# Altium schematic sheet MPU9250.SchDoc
size A4
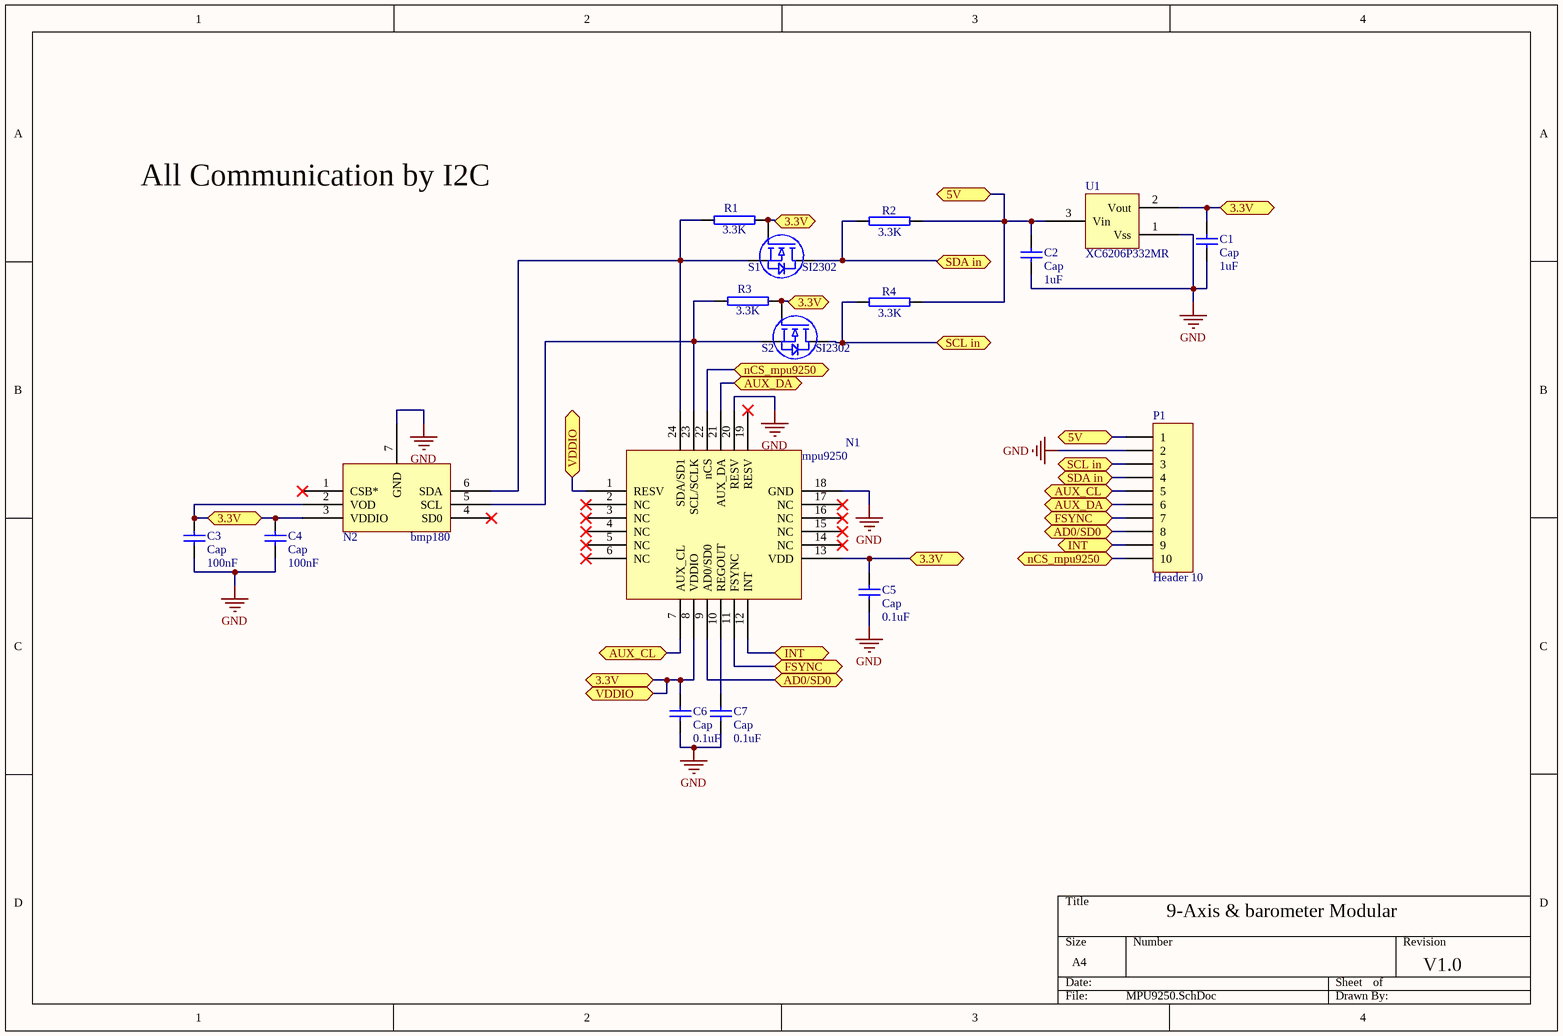
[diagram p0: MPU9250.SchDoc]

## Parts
C1  Cap  value 1uF  [CAPC_0603]
C2  Cap  value 1uF  [CAPC_0603]
C3  Cap  value 100nF  [RAD-0.3]
C4  Cap  value 100nF  [RAD-0.3]
C5  Cap  value 0.1uF  [RAD-0.3]
C6  Cap  value 0.1uF  [RAD-0.3]
C7  Cap  value 0.1uF  [RAD-0.3]
N1  mpu9250  [RM-MPU-9250A]
N2  bmp180
P1  Header 10  [HDR1X10]
R1  3.3K  [RES_0603]
R2  3.3K  [RES_0603]
R3  3.3K  [RES_0603]
R4  3.3K  [RES_0603]
S1  SI2302  [SOT-23]
S2  SI2302  [SOT-23]
U1  XC6206P332MR  [SOT-23]

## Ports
3.3V, 5V, AD0/SD0, AUX_CL, AUX_DA, FSYNC, INT, nCS_mpu9250, SCL in, SDA in (bidir), VDDIO

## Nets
GND: C1.1 C2.1 C3.1 C4.1 C5.1 C6.1 C7.1 N1.18(GND) N1.20(RESV) N2.7(GND) P1.2 U1.1(Vss)
3.3V: C1.2 C3.2 C4.2 C5.2 C6.2 N1.1(RESV) N1.8(VDDIO) N1.13(VDD) N2.2(VOD) N2.3(VDDIO) R1.1 R3.1 S1.1(G) S2.1(G) U1.2(Vout) ; port 3.3V, port VDDIO
5V: C2.2 P1.1 R2.1 R4.1 U1.3(Vin) ; port 5V
AD0/SD0: N1.9(AD0/SD0) P1.8 ; port AD0/SD0
AUX_CL: N1.7(AUX_CL) P1.5 ; port AUX_CL
AUX_DA: N1.21(AUX_DA) P1.6 ; port AUX_DA
FSYNC: N1.11(FSYNC) P1.7 ; port FSYNC
INT: N1.12(INT) P1.9 ; port INT
nCS_mpu9250: N1.22(nCS) P1.10 ; port nCS_mpu9250
SCL in: P1.3 R4.2 S2.3(D) ; port SCL in
SDA in: P1.4 R2.2 S1.3(D) ; port SDA in
NetC7_2: C7.2 N1.10(REGOUT)
NetN1_23: N1.23(SCL/SCLK) N2.5(SCL) R3.2 S2.2(S)
NetN1_24: N1.24(SDA/SD1) N2.6(SDA) R1.2 S1.2(S)

Not connected (* = marked no-connect by the designer): N1 2(NC)* 3(NC)* 4(NC)* 5(NC)* 6(NC)* 14(NC)* 15(NC)* 16(NC)* 17(NC)* 19(RESV)*; N2 1(CSB*)* 4(SD0)*

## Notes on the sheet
- All Communication by I2C
- 9-Axis & barometer Modular
- V1.0

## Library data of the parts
C1-C7 = Cap: Capacitor
N1 = mcp9250
P1 = Header 10: Header, 10-Pin
R1-R4 = RES2
S1 S2 = NMOS
U1 = 662k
